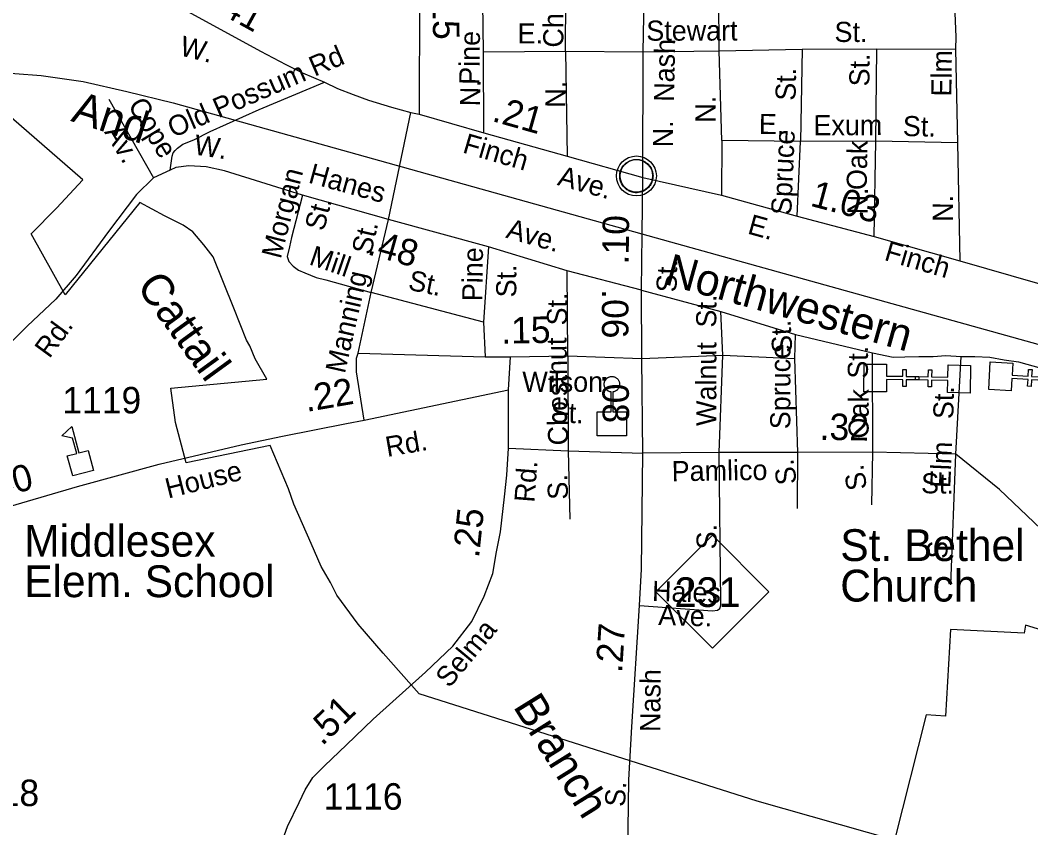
# Model space of a CAD drawing. Extents: x 2220236 to 2384410, y 720751 to 894131.
# Drawn here: x 2233152 to 2237921, y 740224 to 744033 of the extents above; entities that cross this region are included whole.
import ezdxf

# ---------------------------------------------------------------- set-up
doc = ezdxf.new("R2010")
doc.units = 0
doc.layers.add('Default', color=7, linetype='Continuous')

msp = doc.modelspace()

# ---------------------------------------------------------------- linework, layer by layer
at = {"layer": 'Default'}
for p, q in [((2235035.8, 744409.2), (2235034.9, 743591)), ((2235725.7, 743886.9), (2235729.1, 744421.9)), ((2236449.9, 743889.1), (2236446.6, 744439.5)), ((2235338.7, 743884.7), (2235725.7, 743886.9)), ((2235340.4, 743502.9), (2235338.7, 743884.7)), ((2235725.7, 743886.9), (2236091.7, 743884.7)), ((2235725.7, 743886.9), (2235733.2, 743391.8)), ((2236091.7, 743884.7), (2236449.9, 743889.1)), ((2236449.9, 743889.1), (2236841.9, 743897.5)), ((2236463.5, 743466.6), (2236449.9, 743889.1)), ((2236841.9, 743897.5), (2236833.5, 743461.6)), ((2236841.9, 743897.5), (2237193.8, 743898.2)), ((2237189.3, 743462.5), (2237193.8, 743898.2)), ((2237193.8, 743898.2), (2237565.7, 743897.4)), ((2237565.7, 743897.4), (2237575.2, 743455.5)), ((2233570.1, 743660.3), (2233780.5, 743290.6)), ((2234889, 743093.5), (2234995.2, 743597.9)), ((2236463.5, 743466.6), (2236461.6, 743208.7)), ((2236833.5, 743461.6), (2236463.5, 743466.6)), ((2236818.3, 743109.6), (2236833.5, 743461.6)), ((2237189.3, 743462.5), (2236833.5, 743461.6)), ((2237181, 743012.5), (2237189.3, 743462.5)), ((2237575.2, 743455.5), (2237189.3, 743462.5)), ((2237575.2, 743455.5), (2237585.7, 742897.8)), ((2234807.9, 742749.7), (2234889, 743093.5)), ((2235361.2, 742963.9), (2235338.7, 742609.8)), ((2235735.8, 742450.9), (2235732.6, 742851.1)), ((2234746.6, 742462.9), (2234807.9, 742749.7)), ((2235338.7, 742609.8), (2234807.9, 742749.7)), ((2236084.2, 742760.1), (2236458.3, 742659.9)), ((2236084.5, 742437.1), (2236084.2, 742760.1)), ((2236467.9, 742452.9), (2236458.3, 742659.9)), ((2236458.3, 742659.9), (2236810.4, 742551.7)), ((2235338.7, 742609.8), (2235345.6, 742445.7)), ((2236807.8, 742438.2), (2236810.4, 742551.7)), ((2236810.4, 742551.7), (2237173, 742465.3)), ((2234746.6, 742462.9), (2235345.6, 742445.7)), ((2235345.6, 742445.7), (2235464.7, 742445.7)), ((2235735.8, 742450.9), (2235737.5, 742001.8)), ((2236084.5, 742437.1), (2236467.9, 742452.9)), ((2236450.2, 741994.3), (2236467.9, 742452.9)), ((2236467.9, 742452.9), (2236807.8, 742438.2)), ((2237175.3, 741995.4), (2237173, 742465.3)), ((2237566.6, 741986.2), (2237591.9, 742448)), ((2236090, 741992), (2236084.5, 742437.1)), ((2236821.9, 741994.3), (2236807.8, 742438.2)), ((2235455.9, 742015.1), (2235737.5, 742001.8)), ((2235737.5, 742001.8), (2236090, 741992)), ((2235737.5, 742001.8), (2235745.3, 741680.5)), ((2236819.6, 741730.5), (2236821.9, 741994.3)), ((2237170.7, 741747.8), (2237175.3, 741995.4)), ((2237543.5, 741370.1), (2237566.6, 741986.2))]:
    msp.add_line(p, q, dxfattribs=at)
for points in [[(2236089.7, 743291.6), (2236091.7, 743884.7), (2236100.4, 744384.7), (2236135.7, 744463.5), (2236224.4, 744622.2), (2236298.7, 744711.4), (2236462.8, 744802.1), (2236705.2, 744893.4), (2237380.1, 745200.3), (2237789, 745422.4), (2238830.4, 745932.7), (2239176.9, 746116.9), (2239346, 746200.8), (2239469.3, 746283.8), (2239572.7, 746362.7), (2239701.8, 746467.6)], [(2237380.1, 745200.3), (2237424.9, 744983.8), (2237456.8, 744821), (2237474.3, 744709.2), (2237491.9, 744614.9), (2237529.2, 744438.8), (2237542.1, 744327), (2237562.2, 744067.2), (2237567.1, 743955.4), (2237565.7, 743897.4)], [(2233116.5, 744547.9), (2233770.4, 744170.9), (2234285.3, 743887.2), (2234406, 743825), (2234484.6, 743784.7), (2234587, 743740.8), (2234648.5, 743711.6), (2234722.6, 743682.3), (2234794.9, 743656.8), (2234904.5, 743623.8), (2234995.2, 743597.9), (2235034.9, 743591)], [(2235338.7, 743884.7), (2235334.4, 744115.6), (2235332.6, 744159.7), (2235336.7, 744182), (2235334.6, 744210.5), (2235355.2, 744238.9), (2235384.5, 744263.1), (2235442.4, 744287.8), (2235489.2, 744312.5), (2235533, 744341), (2235659.9, 744407.8)], [(2229784.7, 743212.2), (2230034.1, 743256.3), (2231638.9, 743567.2), (2231774.6, 743594.4), (2231890.3, 743619.2), (2232004.1, 743640.2), (2232265.6, 743694.3), (2232405.4, 743725.4), (2232590.9, 743762.9), (2232780.7, 743784.4), (2232962.4, 743793.9), (2233126.5, 743781.3), (2233250.5, 743772.2), (2233448.7, 743743.9), (2233655, 743697.7), (2233873.3, 743643.4), (2236153.5, 743006.3), (2239641.8, 742035), (2241914, 741399.8), (2243637.2, 740920.1)], [(2233859.2, 743325.9), (2233865.3, 743370.4), (2233869.3, 743391.6), (2233873.7, 743407.7), (2233883, 743418.2), (2233893.9, 743429.4), (2233906.5, 743439.7), (2233919.5, 743448), (2233970.7, 743469.9), (2234047.5, 743508.4), (2234279.8, 743612.7), (2234587, 743740.8)], [(2234160.5, 742675.8), (2234061.8, 742917.2), (2234018.8, 742974.3), (2233966, 743035.4), (2233921.5, 743066), (2233832.5, 743110.4), (2233715.8, 743174.2), (2233364.2, 742738.3), (2233203.2, 743025.7), (2233322.8, 743146.5), (2233447.8, 743279.8), (2233035, 743638)], [(2234160.5, 742675.8), (2234061.8, 742917.2), (2234018.8, 742974.3), (2233966, 743035.4), (2233921.5, 743066), (2233832.5, 743110.4), (2233715.8, 743174.2), (2233364.2, 742738.3), (2233203.2, 743025.7), (2233322.8, 743146.5), (2233447.8, 743279.8), (2233035, 743638)], [(2235034.9, 743591), (2235340.4, 743502.9), (2235733.2, 743391.8), (2236089.7, 743291.6)], [(2236084.2, 742760.1), (2235732.6, 742851.1), (2235361.2, 742963.9), (2234889, 743093.5), (2234483.3, 743207.5), (2234115.2, 743323.5), (2234029.2, 743341.8), (2233946.9, 743347.3), (2233886.5, 743338.2), (2233859.2, 743325.9), (2233780.5, 743290.6), (2233700.4, 743211.9), (2233568.5, 743037.2), (2233416.1, 742830), (2233319.2, 742717.2), (2233184.2, 742590.2), (2233093, 742499.5), (2232973.9, 742398.6), (2232801, 742267.2), (2232689.7, 742190.3), (2232530.6, 742085.2), (2232276.8, 741902.5)], [(2236084.2, 742760.1), (2236086.9, 743024.9), (2236089.7, 743291.6)], [(2236089.7, 743291.6), (2236461.6, 743208.7), (2236818.3, 743109.6), (2237181, 743012.5), (2237585.7, 742897.8), (2237952.5, 742792.9), (2238049, 742766.7), (2238252.9, 742711.4), (2238411.3, 742664.7), (2238595.6, 742620.3), (2238695.7, 742601.1), (2238779.6, 742587.8), (2238857.8, 742578.4), (2238943.7, 742575.2), (2239015.7, 742575.7), (2239197.6, 742571.2), (2239957.5, 742549.4), (2241123.5, 742495), (2241221.5, 742485.8), (2241339.5, 742468.7), (2241365.6, 742462.8), (2241409.7, 742459.3)], [(2234483.3, 743207.5), (2234431.5, 743008.9), (2234422.9, 742963.9), (2234410.8, 742919), (2234419.4, 742894.8), (2234440.2, 742874.1), (2234464.3, 742855.1), (2234495.4, 742841.3), (2234548.9, 742820.6), (2234593.8, 742808.5), (2234807.9, 742749.7)], [(2234331.5, 742027.4), (2233934.5, 741945.4), (2233885.2, 742135.6), (2233861.8, 742297.9), (2234315, 742340.6), (2234261, 742435.9), (2234235.2, 742496.9), (2234220, 742523.8), (2234160.5, 742675.8)], [(2234331.5, 742027.4), (2233934.5, 741945.4), (2233885.2, 742135.6), (2233861.8, 742297.9), (2234315, 742340.6), (2234261, 742435.9), (2234235.2, 742496.9), (2234220, 742523.8), (2234160.5, 742675.8)], [(2234774.2, 742146.9), (2234739.3, 742374.9), (2234738.7, 742438.9), (2234746.6, 742462.9)], [(2235456.1, 742290.2), (2235464.7, 742445.7), (2235735.8, 742450.9), (2236084.5, 742437.1)], [(2237173, 742465.3), (2237271.9, 742443.4), (2237326, 742445.7), (2237392.8, 742446.9), (2237460.7, 742448), (2237520, 742451.5), (2237591.9, 742448)], [(2237591.9, 742448), (2237656.3, 742446.9), (2237727.7, 742444.6), (2237795.6, 742431.9), (2237862.3, 742421.5), (2237970.5, 742392.7), (2238291, 742323.6)], [(2232384.7, 741521.8), (2233039.2, 741721.9), (2233422.5, 741834.2), (2233807.5, 741939.6), (2234194.2, 742031.1), (2234389.2, 742071.9), (2234691.3, 742131.3), (2234774.2, 742146.9), (2235456.1, 742290.2)], [(2234109.6, 738638.8), (2234281.3, 739283.5), (2234328.9, 739603.8), (2234349, 739867.4), (2234358.1, 739986.3), (2234383.7, 740147.4), (2234413, 740229.7), (2234468.8, 740343.2), (2234496.2, 740403.6), (2234532.8, 740462.2), (2234587.7, 740517.1), (2234691.9, 740615.9), (2234818.1, 740736.7), (2235063.7, 740957.8), (2235193.1, 741080.7), (2235282.7, 741197.9), (2235341.2, 741316.8), (2235381.5, 741423), (2235399.7, 741525.5), (2235418.9, 741620.6), (2235437.2, 741785.3), (2235448.2, 741887.8), (2235455.9, 742015.1), (2235456.1, 742290.2)], [(2238045.2, 741133.9), (2237895.2, 741180.7), (2237889, 741142.2), (2237542.5, 741159.3), (2237519, 740751.2), (2237427.2, 740757.7), (2237277.5, 740165.9), (2236630, 740350.1), (2235035.2, 740855.9), (2234865.2, 741048.5), (2234746.8, 741185), (2234646.2, 741321.6), (2234616.2, 741381.4), (2234571.5, 741456.2), (2234524.5, 741565.2), (2234443.2, 741751.1), (2234417.5, 741823.7), (2234331.5, 742027.4)], [(2238045.2, 741133.9), (2237895.2, 741180.7), (2237889, 741142.2), (2237542.5, 741159.3), (2237519, 740751.2), (2237427.2, 740757.7), (2237277.5, 740165.9), (2236630, 740350.1), (2235035.2, 740855.9), (2234865.2, 741048.5), (2234746.8, 741185), (2234646.2, 741321.6), (2234616.2, 741381.4), (2234571.5, 741456.2), (2234524.5, 741565.2), (2234443.2, 741751.1), (2234417.5, 741823.7), (2234331.5, 742027.4)], [(2236021.3, 737774.2), (2236016.3, 739866.6), (2236023.2, 740450.5), (2236038.4, 740700.8), (2236075, 741272.2), (2236084.2, 741443.8), (2236090, 741992)], [(2236075, 741272.2), (2236419.1, 741248), (2236442.1, 741251.5), (2236452.8, 741259.2), (2236456.1, 741267.3), (2236457.8, 741276.1), (2236458.3, 741289.5), (2236450.2, 741994.3)], [(2239203.1, 739739.1), (2239091.9, 740085.4), (2238852.3, 740559.2), (2238756.7, 740754.3), (2238695.8, 740871.9), (2238641, 740961.4), (2238606.6, 741009.1), (2238566.3, 741052.7), (2238507.9, 741110.1), (2238437.3, 741185.6), (2238294.2, 741324.5), (2237773, 741819.9), (2237566.6, 741986.2), (2237175.3, 741995.4), (2236821.9, 741994.3), (2236450.2, 741994.3), (2236090, 741992)]]:
    msp.add_lwpolyline(points, dxfattribs=at)
for points in [[(2235982.1, 743311.3), (2235983, 743316.9), (2235984.8, 743323.5), (2235987.7, 743330.7), (2235990.7, 743336.4), (2235994, 743342.2), (2235997.8, 743347.3), (2236001.7, 743351.7), (2236006.3, 743356.3), (2236011.8, 743360.8), (2236017.3, 743364.5), (2236022.2, 743367.4), (2236027.2, 743369.8), (2236032.7, 743372.1), (2236038.3, 743373.9), (2236042.6, 743375.1), (2236047.5, 743375.8), (2236051.6, 743376.6), (2236058, 743376.8), (2236062.4, 743376.7), (2236068.1, 743376.4), (2236073, 743375.7), (2236077.9, 743374.7), (2236082.9, 743373.3), (2236088.1, 743371.4), (2236094.7, 743368.5), (2236101, 743365), (2236106, 743361.4), (2236111.2, 743357.4), (2236114.5, 743354.3), (2236118.6, 743349.9), (2236122.5, 743345.2), (2236125.6, 743340.6), (2236128.7, 743335.6), (2236131.2, 743330.4), (2236133.2, 743325.4), (2236134.8, 743320.4), (2236136, 743315.8), (2236137.1, 743309.8), (2236137.8, 743305.1), (2236138, 743299.1), (2236137.8, 743293.3), (2236137.3, 743287.6), (2236136.3, 743282.1), (2236134.7, 743276), (2236132.8, 743270.1), (2236130.5, 743265), (2236127.3, 743259), (2236124.1, 743253.7), (2236120.6, 743249), (2236116.4, 743244.3), (2236111.1, 743239.3), (2236106.1, 743235.2), (2236101.1, 743231.8), (2236096.7, 743229.3), (2236089.9, 743226), (2236082.8, 743223.3), (2236076.8, 743221.8), (2236070.2, 743220.5), (2236065.8, 743220.1), (2236061.3, 743219.8), (2236055.7, 743219.8), (2236051.5, 743220.2), (2236045.8, 743221), (2236039.9, 743222.3), (2236035.3, 743223.6), (2236030.1, 743225.4), (2236025.5, 743227.4), (2236021.6, 743229.7), (2236014.8, 743233.7), (2236009.2, 743238), (2236004.3, 743242.5), (2235999.9, 743247.4), (2235996.7, 743251.3), (2235993.7, 743255.5), (2235989.6, 743262.6), (2235987.9, 743266.1), (2235986.2, 743270.2), (2235983.6, 743278.4), (2235982.1, 743285.4), (2235981.4, 743290.6), (2235981, 743296.9), (2235981, 743301.6), (2235981.5, 743308)], [(2237240.6, 742410.9), (2237240.4, 742354), (2237316.6, 742353.7), (2237316.7, 742385.7), (2237332.7, 742385.6), (2237332.5, 742353.6), (2237392.7, 742353.3), (2237392.6, 742337.3), (2237332.5, 742337.6), (2237332.3, 742305.6), (2237316.4, 742305.6), (2237316.5, 742337.6), (2237240.4, 742338), (2237240, 742280.3), (2237133.5, 742280.8), (2237134.1, 742411.4)], [(2237527.5, 742277), (2237528.6, 742333.9), (2237452.5, 742335.6), (2237451.8, 742303.6), (2237435.8, 742303.9), (2237436.5, 742335.9), (2237376.4, 742337.3), (2237376.8, 742353.3), (2237436.9, 742351.9), (2237437.6, 742383.9), (2237453.6, 742383.6), (2237452.9, 742351.6), (2237529, 742349.9), (2237530.4, 742407.5), (2237636.8, 742405.2), (2237633.9, 742274.6)], [(2237836, 742415.8), (2237832.8, 742359), (2237908.8, 742354.5), (2237910.7, 742386.4), (2237926.7, 742385.5), (2237924.8, 742353.6), (2237984.8, 742350.1), (2237983.9, 742334.1), (2237923.9, 742337.6), (2237922, 742305.6), (2237906, 742306.6), (2237907.9, 742338.5), (2237831.9, 742343), (2237828.4, 742285.4), (2237722.1, 742291.6), (2237729.8, 742422)], [(2235940, 742280.2), (2235937.2, 742280.6), (2235934.4, 742281.2), (2235931.6, 742282.1), (2235928.9, 742283.2), (2235926.6, 742284.4), (2235924.6, 742285.5), (2235922.7, 742286.8), (2235920.5, 742288.5), (2235919, 742289.8), (2235917.4, 742291.5), (2235915.8, 742293.3), (2235914.5, 742294.9), (2235913.2, 742296.9), (2235912, 742299), (2235911, 742300.9), (2235910.1, 742302.8), (2235909.5, 742304.4), (2235908.9, 742306.4), (2235908.3, 742308.6), (2235907.9, 742310.8), (2235907.7, 742312.8), (2235907.5, 742315.2), (2235907.5, 742317.9), (2235907.7, 742320), (2235908, 742322.3), (2235908.5, 742324.9), (2235909, 742326.8), (2235909.6, 742328.8), (2235910.3, 742330.6), (2235911.1, 742332.3), (2235912.1, 742334.1), (2235913.1, 742335.9), (2235914.4, 742337.8), (2235916.4, 742340.4), (2235918.1, 742342.2), (2235919.9, 742343.8), (2235921.4, 742345.1), (2235922.9, 742346.3), (2235924.9, 742347.5), (2235926.6, 742348.6), (2235928.9, 742349.7), (2235931.1, 742350.6), (2235934, 742351.5), (2235936.6, 742352.2), (2235939.4, 742352.7), (2235942, 742352.9), (2235944, 742352.9), (2235946.9, 742352.8), (2235949.8, 742352.4), (2235952.5, 742351.9), (2235954.7, 742351.3), (2235956.8, 742350.7), (2235959.2, 742349.6), (2235961.5, 742348.5), (2235963.8, 742347.1), (2235966.1, 742345.5), (2235968.4, 742343.6), (2235970.3, 742341.8), (2235971.8, 742340), (2235973.1, 742338.5), (2235974.7, 742336), (2235975.9, 742334.1), (2235977, 742332.1), (2235977.9, 742330), (2235978.6, 742327.8), (2235979.4, 742325.3), (2235979.8, 742323.1), (2235980.2, 742320.4), (2235980.4, 742318.3), (2235980.5, 742315.9), (2235980.3, 742313.6), (2235980.2, 742311.5), (2235979.7, 742308.9), (2235979.1, 742306.6), (2235978.4, 742304.3), (2235977.5, 742302.1), (2235976.5, 742299.9), (2235975.3, 742297.7), (2235973.7, 742295.2), (2235972.2, 742293.3), (2235970.4, 742291.3), (2235968.1, 742289.1), (2235966.2, 742287.5), (2235964.4, 742286.2), (2235962.1, 742284.8), (2235959.9, 742283.6), (2235957.7, 742282.6), (2235955.8, 742281.9), (2235953.5, 742281.2), (2235950.9, 742280.6), (2235949.2, 742280.4), (2235948, 742280.2), (2235948, 742186.7), (2236013.5, 742186.7), (2236013.5, 742073.3), (2235874.4, 742073.3), (2235874.4, 742186.7), (2235940, 742186.7)], [(2233399.5, 741883.6), (2233374.1, 741978.1), (2233418.6, 741990.1), (2233399.2, 742062.6), (2233347.5, 742073.8), (2233394.6, 742116.7), (2233427.9, 741992.5), (2233472.4, 742004.4), (2233497.7, 741909.9)], [(2236151.9, 741337.7), (2236418.3, 741604.1), (2236684.7, 741337.7), (2236418.3, 741071.3)]]:
    msp.add_lwpolyline(points, close=True, dxfattribs=at)
for centre, radius in [((2236059.7, 743298.9), 94.3), ((2236059.4, 743299.2), 76.7)]:
    msp.add_circle(centre, radius, dxfattribs=at)

# ---------------------------------------------------------------- texts
for s, height, rotation, p in [('Chesnut', 95, 89.9867, (2235715.1, 743904.4)), ('.15', 125, 270.681, (2235097.3, 744173.2)), ('.41', 125, 331.1464, (2234053.6, 744086.2)), ('E.', 95, 359.8257, (2235498.7, 743923.9)), ('Stewart', 95, 0.1239, (2236106.5, 743936.6)), ('St.', 95, 359.8696, (2236994.5, 743930.9)), ('Pine', 95, 89.2014, (2235318.3, 743728.1)), ('Old Possum Rd', 95, 23.3869, (2233873.4, 743477.5)), ('W.', 95, 345.9576, (2233899.3, 743869.1)), ('Nash', 95, 88.8903, (2236237.1, 743647.9)), ('Elm', 95, 89.1604, (2237545.7, 743673)), ('St.', 95, 89.4, (2237159.1, 743720.9)), ('St.', 95, 88.9005, (2236810.7, 743653.1)), ('N.', 95, 88.9151, (2235321.9, 743626.6)), ('N.', 95, 89.9867, (2235725, 743620.7)), ('And', 150, 342.0647, (2233386.8, 743558.9)), ('Cope', 95, 301.3306, (2233657.5, 743632.5)), ('.21', 125, 344.2007, (2235373.6, 743558.5)), ('N.', 95, 89.9867, (2236432.9, 743549.9)), ('E.', 95, 359.2248, (2236637, 743497)), ('Exum', 95, 0.1422, (2236895.2, 743490.5)), ('N.', 95, 89.9867, (2236232.3, 743433.7)), ('St.', 95, 358.9705, (2237316.3, 743487.1)), ('Av.', 95, 301.3306, (2233546.3, 743506.2)), ('W.', 95, 351.3124, (2233967.6, 743400.8)), ('Finch', 95, 343.6992, (2235234.9, 743410.3)), ('Spruce', 95, 87.5215, (2236790.2, 743113.3)), ('Oak', 95, 88.9493, (2237146.3, 743231.6)), ('Hanes', 95, 344.5758, (2234507.2, 743268.3)), ('Morgan', 95, 75.6197, (2234381, 742904.1)), ('Ave.', 95, 344.4704, (2235682.6, 743256.7)), ('1.03', 125, 345.0225, (2236875.4, 743159)), ('N.', 95, 88.9493, (2237150.1, 743117.2)), ('St.', 95, 75.6197, (2234585, 743034.7)), ('N.', 95, 89.7048, (2237553, 743082.5)), ('.10', 125, 89.4108, (2236023, 742881.3)), ('E.', 95, 344.4704, (2236579.8, 743028)), ('St.', 95, 77.0387, (2234807.3, 742922.8)), ('Ave.', 95, 343.9976, (2235439.5, 743008.6)), ('.48', 125, 344.1959, (2234785, 742930.4)), ('Mill', 95, 341.0875, (2234510.4, 742882.8)), ('Finch', 95, 343.6992, (2237224.7, 742903.1)), ('Pine', 95, 89.2014, (2235332.4, 742707.4)), ('Northwestern', 150, 344.4404, (2236187.1, 742790.1)), ('St.', 95, 89.7987, (2235492.8, 742725.9)), ('St.', 95, 88.6876, (2236249.1, 742749.2)), ('Cattail', 150, 306.0678, (2233696.9, 742777.8)), ('Manning', 95, 77.1524, (2234683.6, 742363.3)), ('St.', 95, 348.519, (2234978.4, 742762.8)), ('St.', 95, 89.3921, (2235732.4, 742593.3)), ('.06', 125, 270.0505, (2235896.7, 742764.6)), ('St.', 95, 89.4639, (2236436.3, 742583.4)), ('.15', 125, 1.0953, (2235423, 742507.4)), ('Rd.', 95, 53.7485, (2233289.5, 742434.3)), ('St.', 95, 93.4893, (2236796, 742466.1)), ('Chestnut', 95, 90.9763, (2235738.1, 742028.6)), ('Walnut', 95, 89.9774, (2236436.8, 742119.4)), ('Spruce', 95, 89.921, (2236786, 742104.1)), ('St.', 95, 89.7369, (2237152, 742342.6)), ('.22', 125, 9.8048, (2234503, 742185.4)), ('Wilson', 95, 0.0466, (2235521.4, 742280.2)), ('.08', 125, 270.7037, (2235897.9, 742365.1)), ('Oak', 95, 89.7369, (2237155.2, 742060.3)), ('St.', 95, 88.722, (2237555.2, 742151.3)), ('St.', 95, 358.1229, (2235653.9, 742136.8)), ('.32', 125, 359.1219, (2236923.8, 742054.3)), ('Rd.', 95, 9.8048, (2234884, 741973.4)), ('Elm', 95, 87.5202, (2237540.6, 741825.2)), ('Pamlico', 95, 0.7854, (2236226.7, 741858.9)), ('.40', 125, 15.0014, (2232997, 741764.8)), ('House', 95, 14.2244, (2233849.9, 741776.9)), ('Rd.', 95, 85.5684, (2235578, 741756.6)), ('S.', 95, 98.3604, (2236817.1, 741849.3)), ('S.', 95, 99.4399, (2237149, 741824.3)), ('S.', 95, 91.7618, (2235737.3, 741773.3)), ('St.', 95, 359.1219, (2237402.6, 741802.4)), ('.25', 125, 83.9866, (2235316.5, 741494.2)), ('S.', 95, 89.9774, (2236438.6, 741537.5)), ('S.', 95, 87.5202, (2237526.1, 741491.4)), ('Hales', 95, 358.2073, (2236132.4, 741294.6)), ('Ave.', 95, 358.2073, (2236162, 741181.5)), ('Selma', 95, 50.369, (2235176.7, 740879.8)), ('.27', 125, 86.332, (2235991.9, 740952.9)), ('Nash', 95, 89.5904, (2236172.1, 740676)), ('.51', 125, 44.1025, (2234576.4, 740607.3)), ('Branch', 150, 301.8975, (2235475.3, 740796.3)), ('S.', 95, 86.5052, (2236005.1, 740321.3))]:
    msp.add_text(s, height=height, rotation=rotation, dxfattribs=at).set_placement(p)
for s, height, p in [('1119', 125, (2233350.9, 742178.8)), ('Middlesex', 150, (2233170.5, 741503.1)), ('St. Bethel', 150, (2237021.8, 741482.5)), ('Elem. School', 150, (2233170.5, 741312.1)), ('Church', 150, (2237021.8, 741291.5)), ('231', 140, (2236239.2, 741265.9)), ('1118', 125, (2232869.1, 740326.5)), ('1116', 125, (2234584.2, 740309.6))]:
    msp.add_text(s, height=height, dxfattribs=at).set_placement(p)

doc.saveas('drawing.dxf')
